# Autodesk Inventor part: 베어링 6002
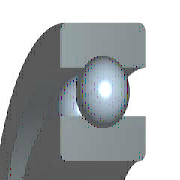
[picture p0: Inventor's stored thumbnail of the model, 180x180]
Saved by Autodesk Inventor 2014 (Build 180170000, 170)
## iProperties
Created: 2012-02
Part Number: 베어링 6002
Material: 강철, 연강
Description: 깊은 그루브 볼 베어링
Document SubType Name: Modeling
Standard: KS B 2023
Designer: mduedu
Standards Organization: KS
Language: ko-KR
Size Designation: 6002 - 15 x 32 x 9
Categories: <MemberInstance><Categories><Category DisplayName="샤프트 부품" InternalName="7f7aeb1f-a693-4053-b835-cee3144e0d98" Mnemonic="SHFT"><Category DisplayName="베어링" Inter
Density: 7.86 g/cm^3
Mass: 27.6801 g
Surface Area: 39.9079 cm^2
Volume: 3.52164 cm^3
Appearance: Pink
IsCustomPart: 1
Author: mduedu
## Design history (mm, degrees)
sketch "스케치" dims "d0" = 4.42 (= -0.26 x WD + 0.26 x BD)
  geometry: L1 (2.29, 11.75)-(6.71, 11.75); L2 (4.5, 11.75)-(4.5, 9.54); L3 (4.5, 11.75)-(4.5, 13.96); L4 (2.858, 10.271)-(0, 10.271); L5 (0, 7.5)-(9, 7.5); L6 (2.858, 13.229)-(0, 13.229); L7 (0, 16)-(9, 16); L8 (9, 7.5)-(9, 10.271); L9 (6.142, 10.271)-(9, 10.271); L10 (6.142, 13.229)-(9, 13.229); L11 (9, 16)-(9, 13.229); L12 (-1.4, 0)-(8.4, 0) reference; L13 (0, -0.3)-(0, 5.3) reference
  constraints: 22 end point, 4 point on line, 2 collinear, 2 perpendicular, 2 symmetric about line, 1 midpoint, 1 parallel, 14 other
  dimensions: "d9" = 15 diameter of L5 L12 (= WD); "d11" = 32 diameter of L7 L12 (= BD); "d12" = 9 distance between parallel lines of L8 L13 (= KB); "d13" = 20.542 diameter of L9 L12 (= 0.326 x BD + 0.674 x WD)
revolve "본체" stored, may be unused: angle "d6" = 90 deg
revolve "볼" stored, may be unused: angle "d7" = 90 deg
pattern_circular "IDS_ARRAYBALL[SIMPL:T]" dims angle "d3" = 360 deg
body "Solid1"
fillet "모깎기1" dims "d1" = 0.3 (= KRS)
other parameters: "WD" = 15 [user parameter; used in 5 equation terms], "BD" = 32 [user parameter; used in 5 equation terms], "KB" = 9 [user parameter; used in 1 equation term], "KRS" = 0.3 [user parameter; used in 1 equation term], "d4" = 0, "d5" = 0, "d8" = 0, "d14" = 0, "d15" = 0, "BBA" = 0 [user parameter], "BC0" = 2850000 [user parameter], "BC" = 5590000 [user parameter], "BR" = 16 (= 0.5 x BD) [user parameter], "WR" = 7.5 (= 0.5 x WD) [user parameter]
